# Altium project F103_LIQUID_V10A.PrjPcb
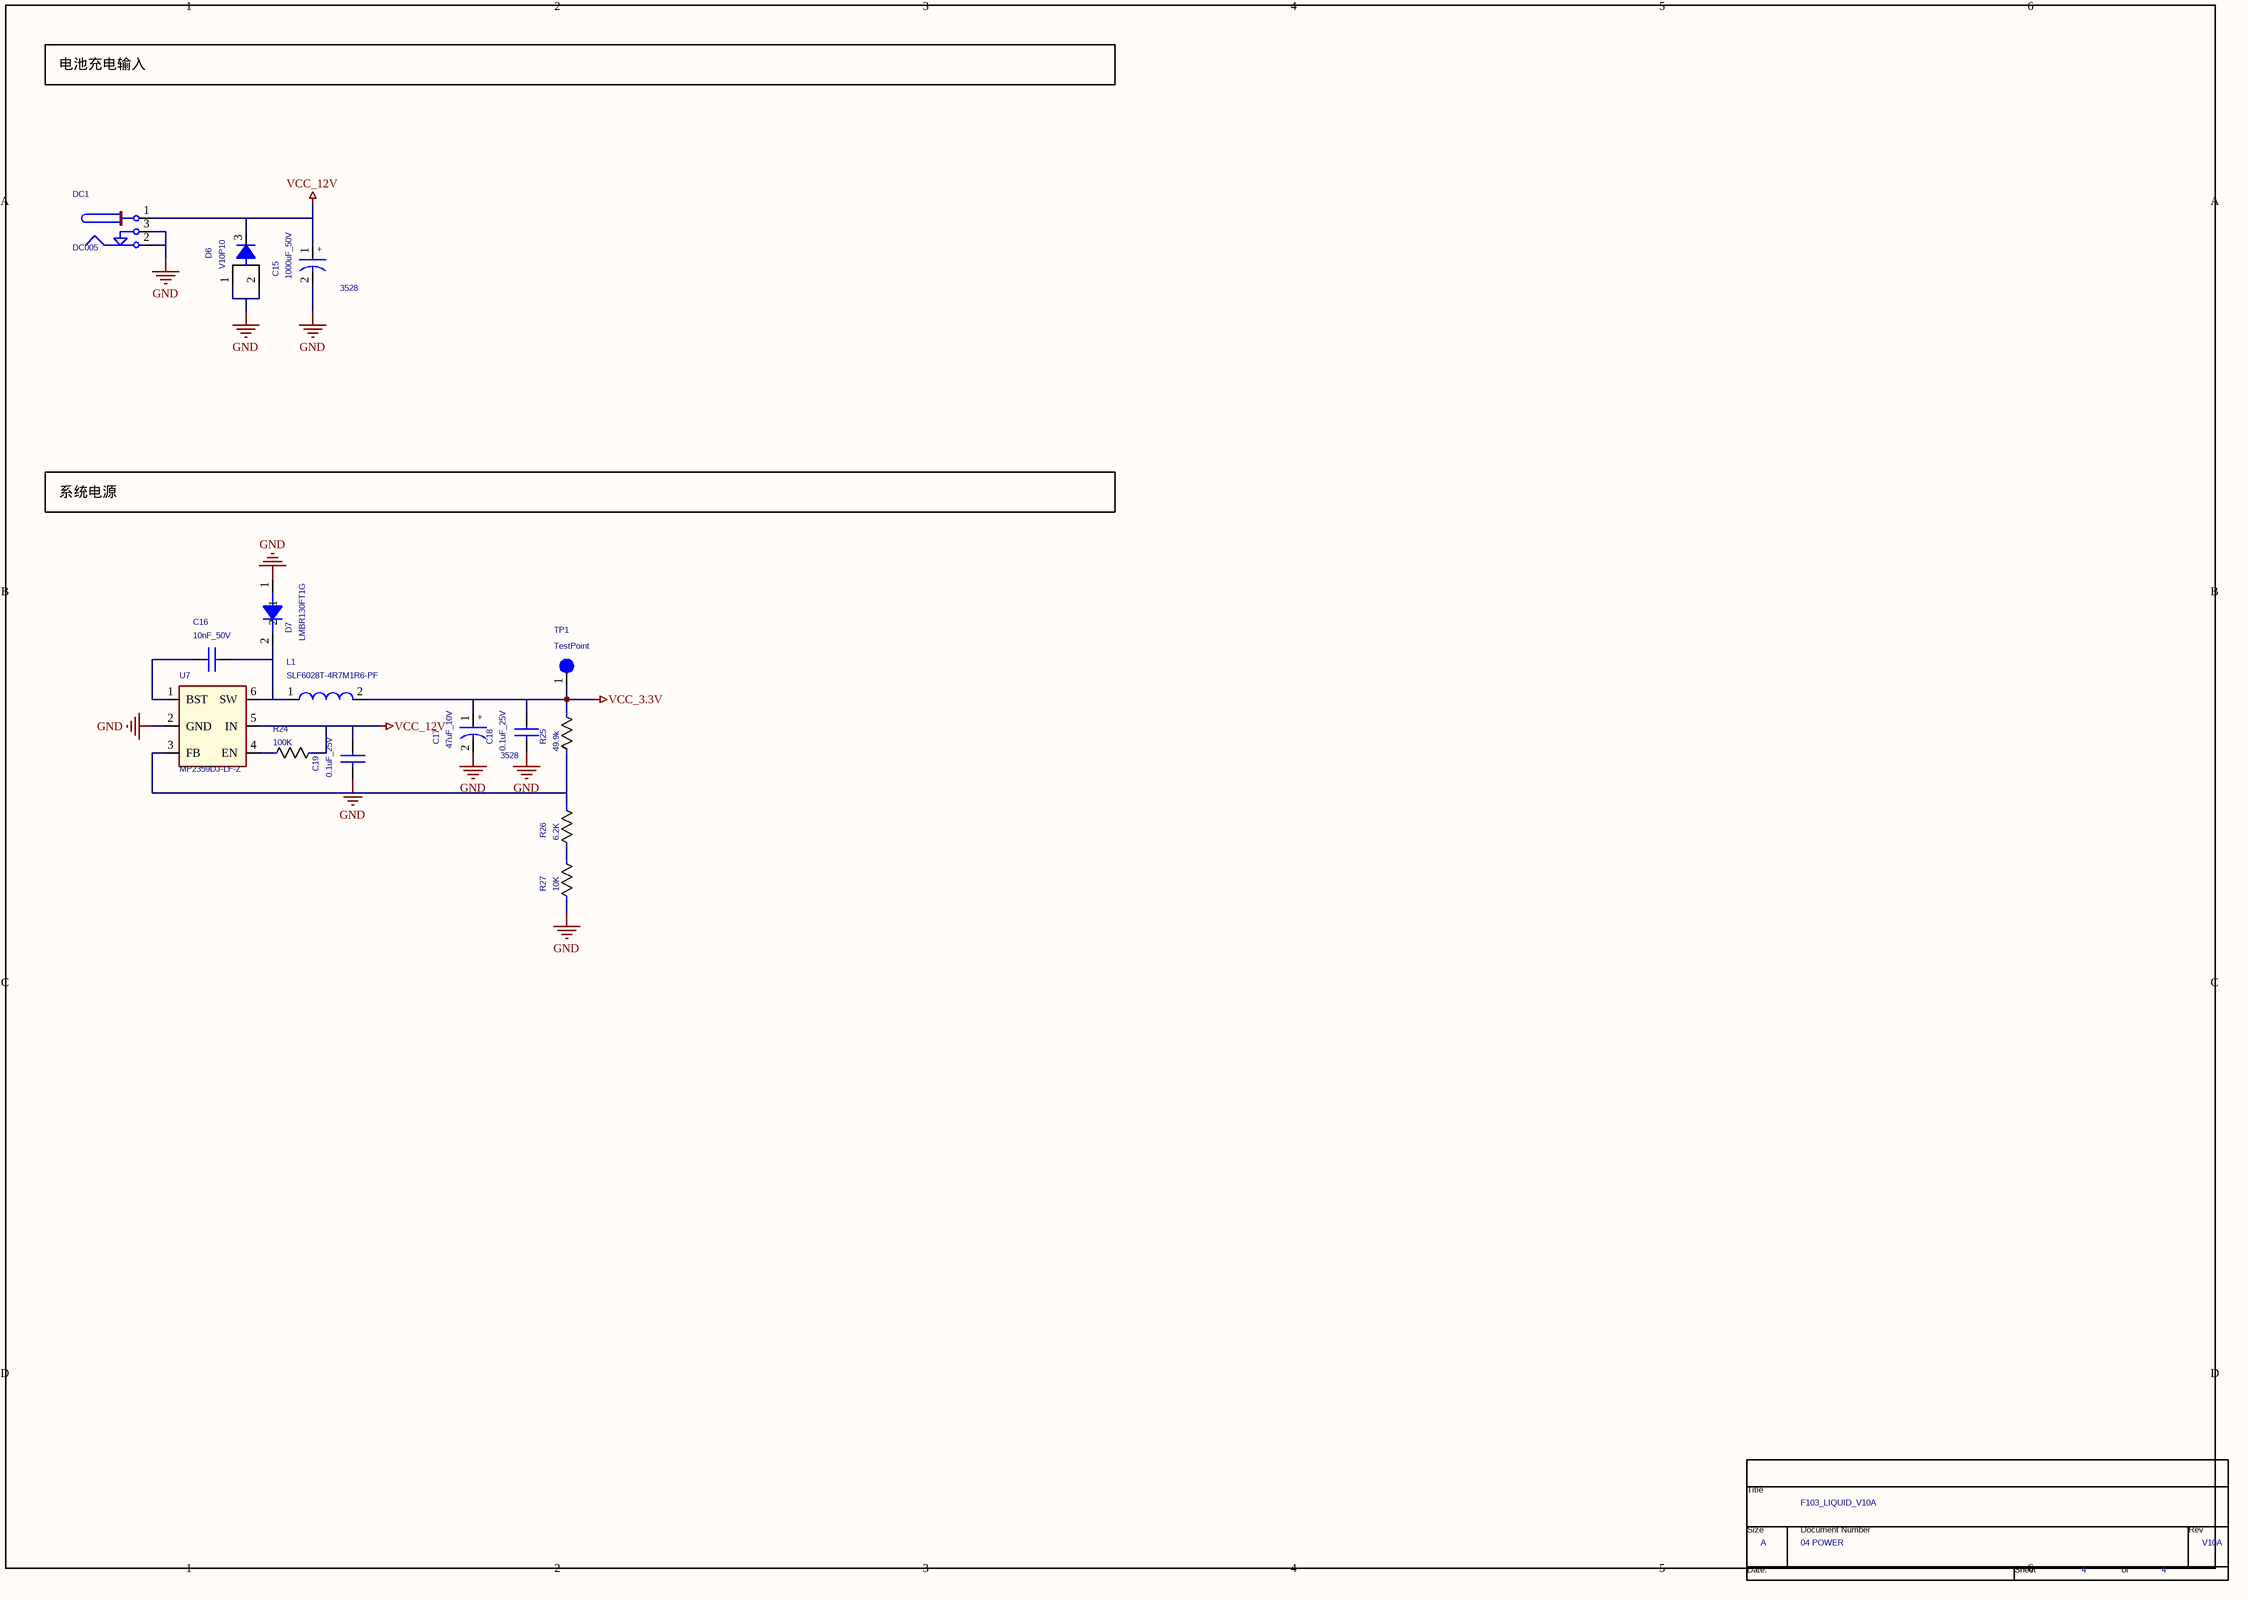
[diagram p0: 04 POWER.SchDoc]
4 sheets, 82 parts. Net scope: global (net labels, ports and power ports of the same name join across sheets).
Board file: F103_LIQUID_V10A.PcbDoc
Sheets:
  04 POWER.SchDoc
  03 RELAY.SchDoc
  02 MCU&TFT.SchDoc
  01 COVER.SchDoc

## Sheet 04 POWER.SchDoc
size 420 x 297 mm

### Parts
(Parts that share a designator on the sheet are numbered #1, #2 ... from top to bottom, then left to right.)
*#1  Doc: 04 POWER  RevCode: V10A  Title: F103_LIQUID_V10A  Page Size: A  Page Number: 4  (hidden comment: TitleBlock0)  (graphical)
C15  1000uF_50V  Shape: 3528  [CT_3528_IPC]
C16  10nF_50V  [C0603]
C17  47uF_10V  Shape: 3528  [CT_3528_IPC]
C18  0.1uF_25V  [C0603]
C19  0.1uF_25V  [C0603]
D6  V10P10  [TO-227A]
D7  LMBR130FT1G  [SOD123]
DC1  DC005  [DC005]
L1  SLF6028T-4R7M1R6-PF  [L6028]
R24  100K  [R0603]
R25  49.9k  [R0603]
R26  6.2K  [R0603]
R27  10K  [R0603]
TP1  TestPoint  [TP-0R75]
U7  MP2359DJ-LF-Z  [TSOT23-6]

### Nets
GND: C15.2 C17.2 C18.2 C19.2 D6.1(ANODE_1) D6.2(ANODE_2) D7.1 DC1.2 DC1.3 R27.2 U7.2(GND)
VCC_3.3V: C17.1 C18.1 L1.2 R25.1 TP1.1
VCC_12V: C15.1 C19.1 D6.3(CATHODE) DC1.1 R24.1 U7.5(IN)
NetC16_1: C16.1 U7.1(BST)
NetC16_2: C16.2 D7.2 L1.1 U7.6(SW)
NetR24_2: R24.2 U7.4(EN)
NetR25_2: R25.2 R26.1 U7.3(FB)
NetR26_2: R26.2 R27.1

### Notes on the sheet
- 电池充电输入
- 系统电源

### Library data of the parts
C15 = CAPT_100UF_3528_6r3V_10%_LXXXX: Cap,50V,10x13,ESK337M1HG13RR; GRN: LHR; EP#: P10100000000041; MFGI 2#: KEM: T494B107K006ATH; MFGI 1#: AVX: TPSB107K006R; Board Option: Base; Corporation: SAMXON
C16 = CAP NP_2: CAP,CERM,50V,+/-10%,X7R,0603; Corporation: FH
C17 = TMP_154254: CAP,TAN,TAJB476K010RNJ; EPI#: P10100000000041; Board Option: Base; MFG 2#: KEM: T494B107K006ATH; MFG 1#: AVX: TPSB107K006R; GRN: LHR; Corporation: AVX
C18 C19 = CAP NP: CAP,CERM,+/-10%,X7R,0603; Corporation: FH
D6 = DIODE13_6: Barrier Schottky Rectifier; Corporation: VISHAY; Type: DIODE
D7 = DIODE13_0: SURFACE MOUNT SCHOTTKY BARRIER RECTIFIER; Type: DIODE; Corporation: LRC
DC1 = DC005: Corporation: LC
L1 = INDUCTOR_0
R24-R27 = R_Generic: RES,1%,0.1W,0603; P/N #3: CR10-103J-T; P/N #1: RK73H1JT1002F; Mfg #1: KOA SPEER; Corporation: FH
TP1 = TestPoint_0: Note: NI
U7 = MP2359DJ-LF-Z: 1.2A, 24V, 1.4MHz Step-Down Converter in a TSOT23-6; Corporation: MPS

## Sheet 03 RELAY.SchDoc
size 420 x 297 mm
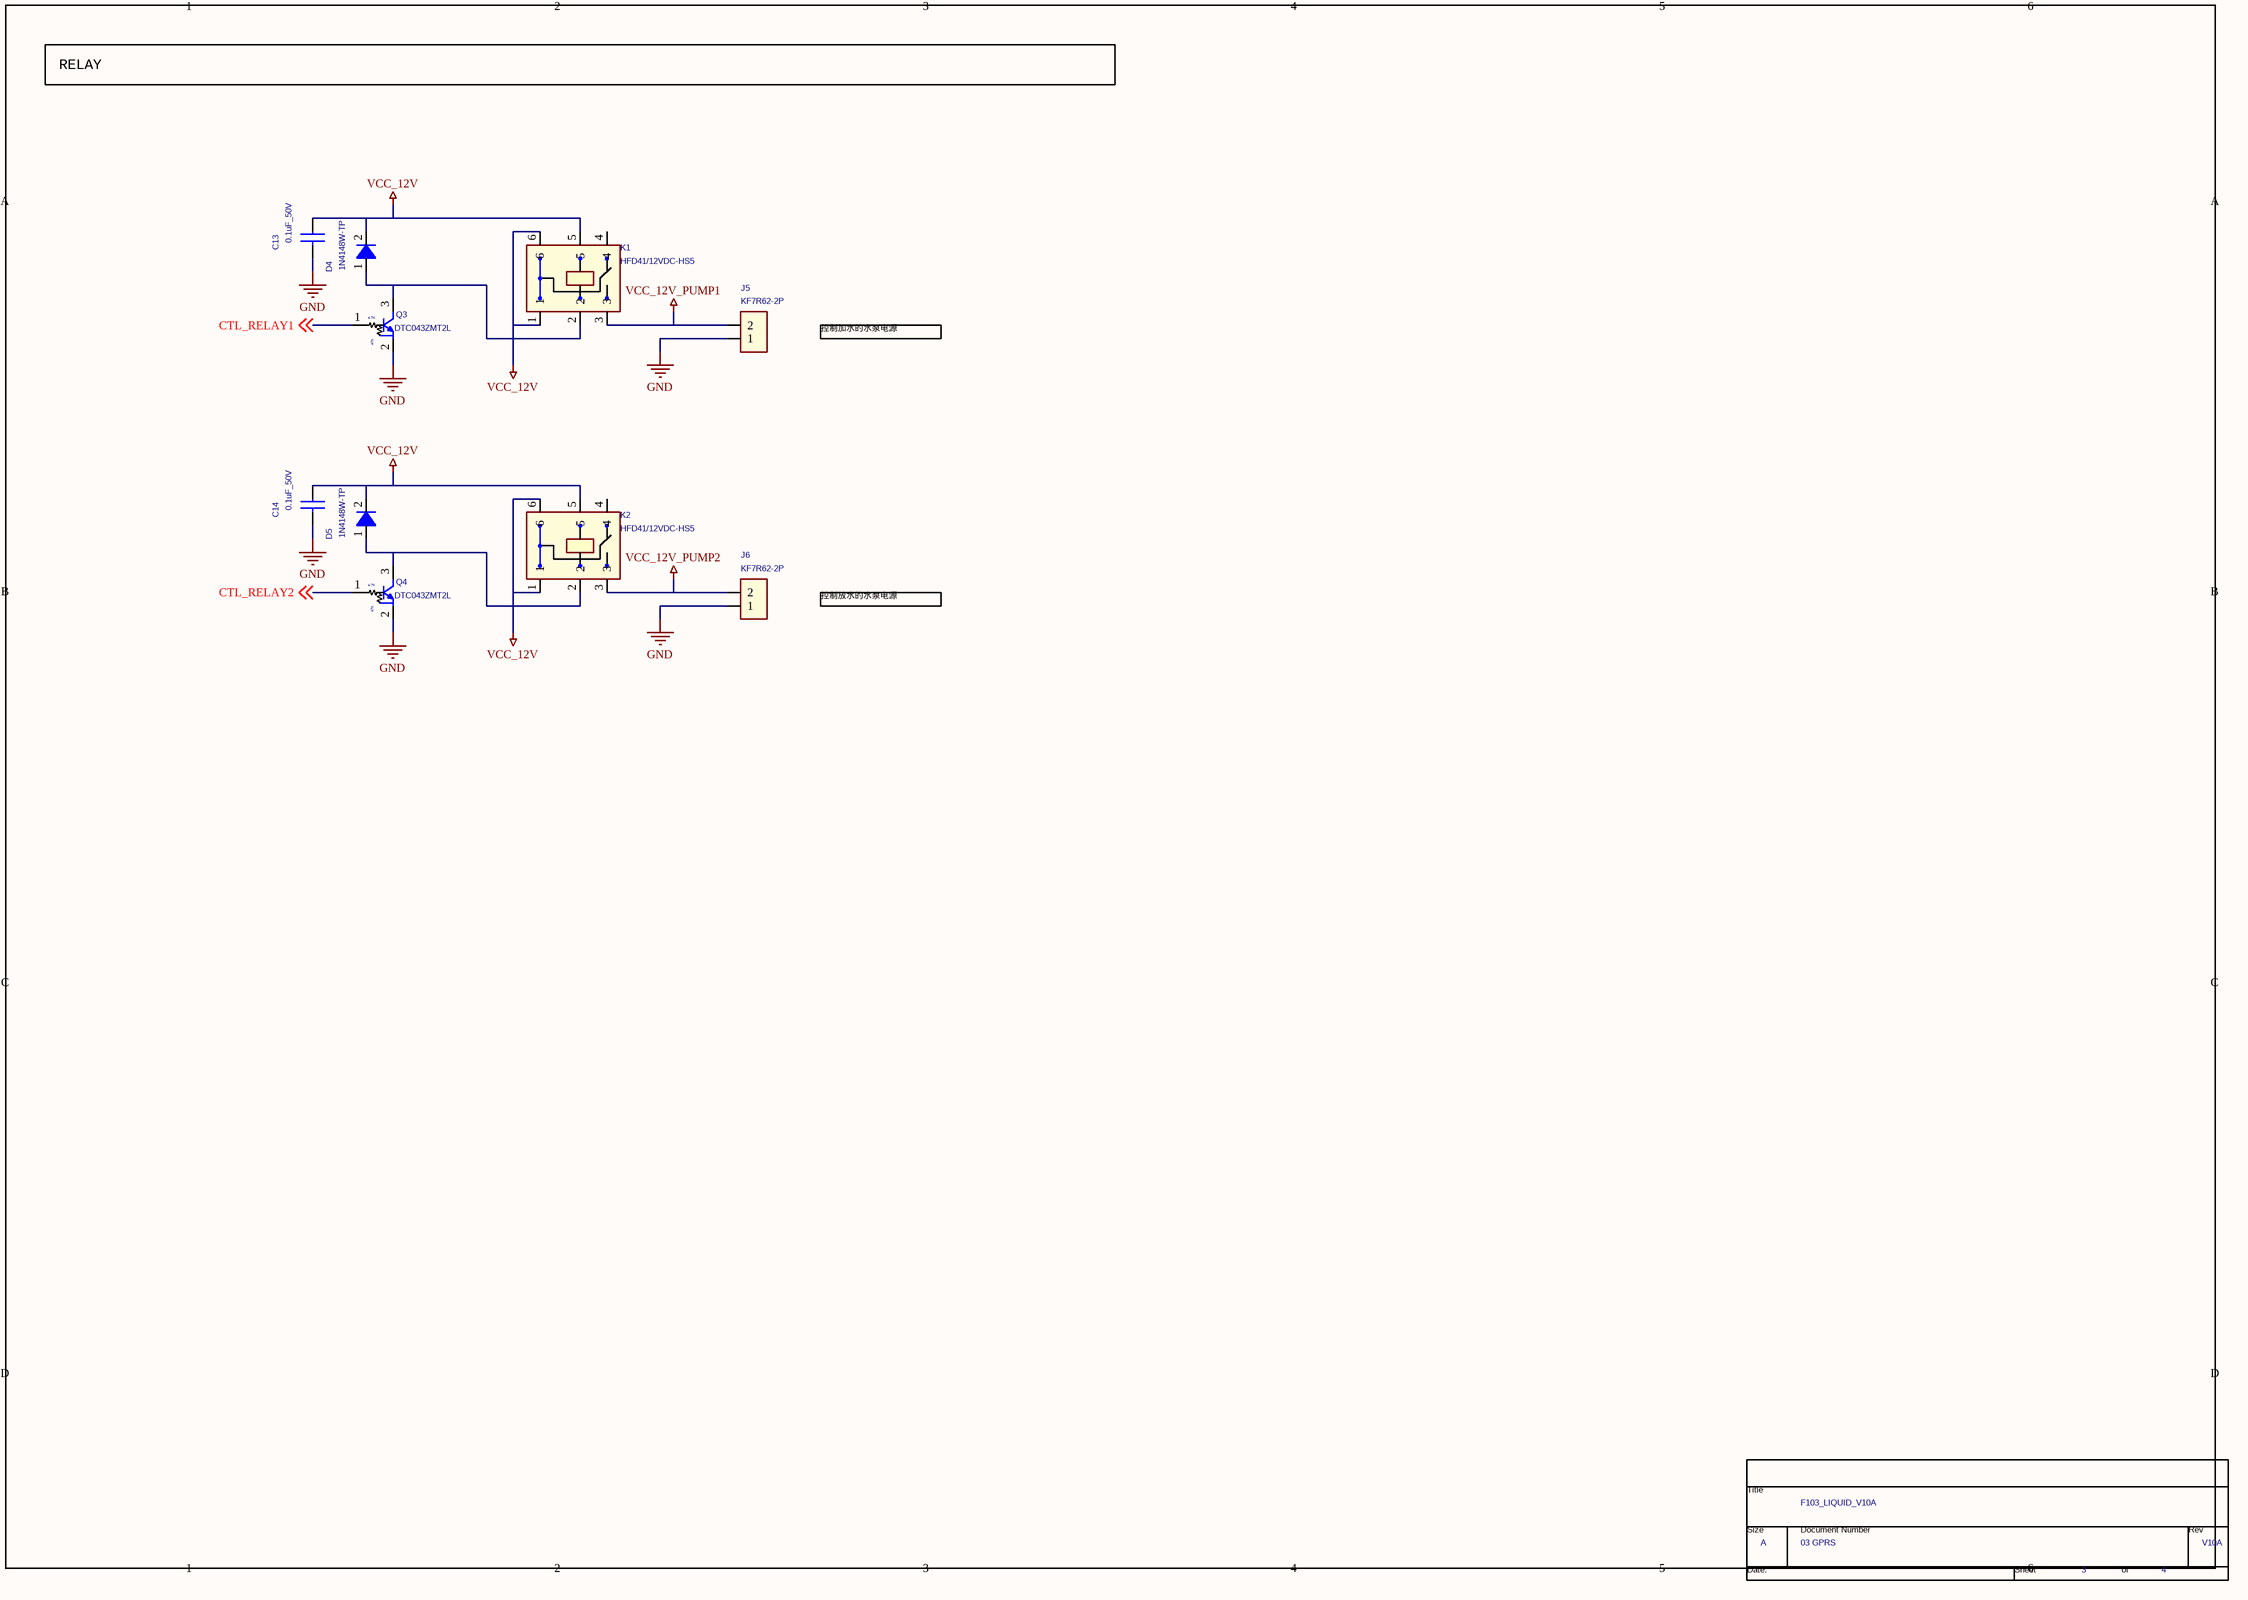
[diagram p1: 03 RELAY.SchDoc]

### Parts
(Parts that share a designator on the sheet are numbered #1, #2 ... from top to bottom, then left to right.)
*#2  Doc: 03 GPRS  RevCode: V10A  Title: F103_LIQUID_V10A  Page Size: A  Page Number: 3  Page Count: 4  (hidden comment: TitleBlock0)  (graphical)
C13  0.1uF_50V  [C0603]
C14  0.1uF_50V  [C0603]
D4  1N4148W-TP  [SOD123]
D5  1N4148W-TP  [SOD123]
J5  KF7R62-2P  [KF7R62-2P]
J6  KF7R62-2P  [KF7R62-2P]
K1  HFD41/12VDC-HS5  [HF32FA-G/005-HSL1]
K2  HFD41/12VDC-HS5  [HF32FA-G/005-HSL1]
Q3  DTC043ZMT2L  [SOT-723]
Q4  DTC043ZMT2L  [SOT-723]

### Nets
GND: C13.2 C14.2 J5.1 J6.1 Q3.2 Q4.2
VCC_12V: C13.1 C14.1 D4.2(CATHODE) D5.2(CATHODE) K1.1 K1.5 K1.6 K2.1 K2.5 K2.6
VCC_12V_PUMP1: J5.2 K1.3
VCC_12V_PUMP2: J6.2 K2.3
CTL_RELAY1: Q3.1 ; off-sheet CTL_RELAY1
CTL_RELAY2: Q4.1 ; off-sheet CTL_RELAY2
NetD4_1: D4.1(ANODE) K1.2 Q3.3
NetD5_1: D5.1(ANODE) K2.2 Q4.3

Not connected (* = marked no-connect by the designer): K1 4; K2 4

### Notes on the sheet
- RELAY
- 控制加水的水泵电源
- 控制放水的水泵电源

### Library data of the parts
C13 C14 = CAP NP_Dup1: CAP,CERM,+/-10%,X7R,0603; Corporation: FH
D4 D5 = DIODE13_7: High Speed Switching Diode 400mW; Corporation: MCC
J5 J6 = HDR_1: Corporation: CIXI MEIGAN
K1 K2 = HF32FA-G/005-HSL1_0: SPST; Corporation: HF
Q3 Q4 = DTC043ZMT2L: Type: NPN; Corporation: ROHM

## Sheet 02 MCU&TFT.SchDoc
size 420 x 297 mm
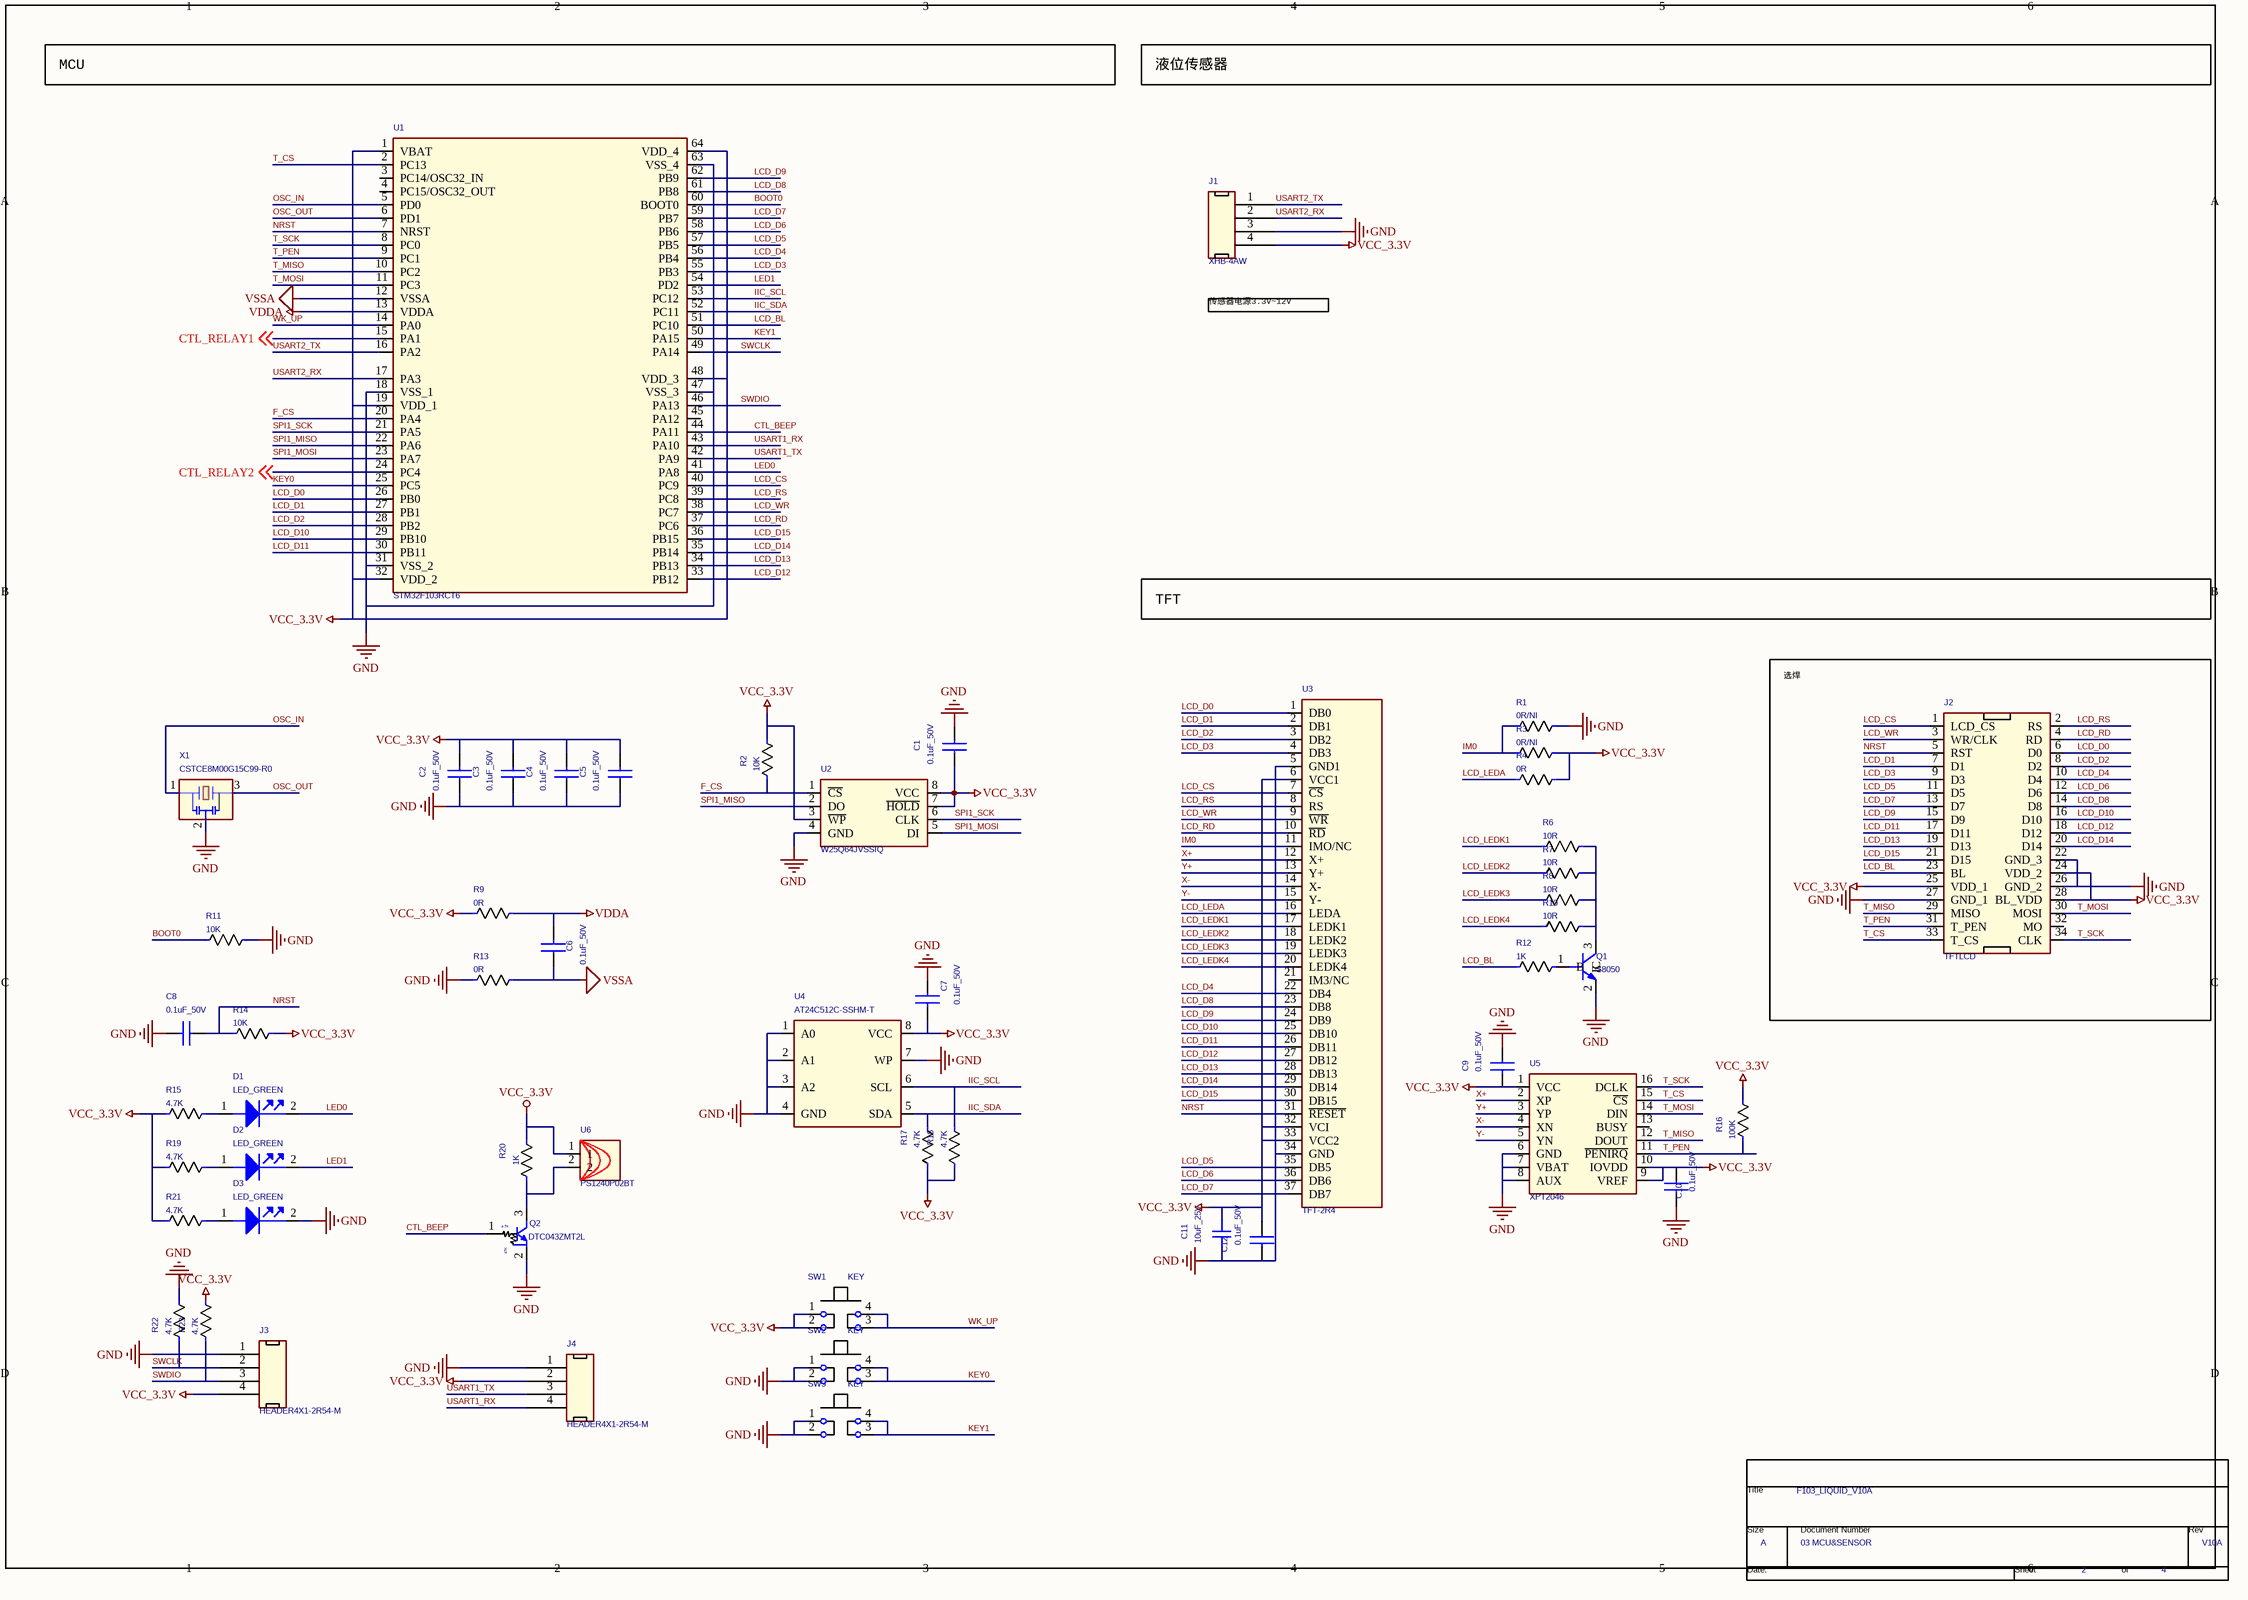
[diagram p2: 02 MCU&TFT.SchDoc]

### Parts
(Parts that share a designator on the sheet are numbered #1, #2 ... from top to bottom, then left to right.)
*#3  Doc: 03 MCU&SENSOR  RevCode: V10A  Title: F103_LIQUID_V10A  Page Size: A  Page Number: 2  Page Count: 4  (hidden comment: TitleBlock0)  (graphical)
C1  0.1uF_50V  [C0603]
C2  0.1uF_50V  [C0603]
C3  0.1uF_50V  [C0603]
C4  0.1uF_50V  [C0603]
C5  0.1uF_50V  [C0603]
C6  0.1uF_50V  [C0603]
C7  0.1uF_50V  [C0603]
C8  0.1uF_50V  [C0603]
C9  0.1uF_50V  [C0603]
C10  0.1uF_50V  [C0603]
C11  10uF_25V  [C0805]
C12  0.1uF_50V  [C0603]
D1  LED_GREEN  [LED0805]
D2  LED_GREEN  [LED0805]
D3  LED_GREEN  [LED0805]
J1  XHB-4AW  [XHB-4AW]
J2  TFTLCD  [TFTLCD_3R5]
J3  HEADER4X1-2R54-M  [HEADER4X1-2R54-M]
J4  HEADER4X1-2R54-M  [HEADER4X1-2R54-M]
Q1  S8050  [SOT23-3]
Q2  DTC043ZMT2L  [SOT-723]
R1  0R/NI  [R0603]
R2  10K  [R0603]
R3  0R/NI  [R0603]
R4  0R  [R0603]
R6  10R  [R0603]
R7  10R  [R0603]
R8  10R  [R0603]
R9  0R  [R0603]
R10  10R  [R0603]
R11  10K  [R0603]
R12  1K  [R0603]
R13  0R  [R0603]
R14  10K  [R0603]
R15  4.7K  [R0603]
R16  100K  [R0603]
R17  4.7K  [R0603]
R18  4.7K  [R0603]
R19  4.7K  [R0603]
R20  1K  [R0603]
R21  4.7K  [R0603]
R22  4.7K  [R0603]
R23  4.7K  [R0603]
SW1  KEY  [SPST]
SW2  KEY  [SPST]
SW3  KEY  [SPST]
U1  STM32F103RCT6  [QFP-64]
U2  W25Q64JVSSIQ  [SO-8-W]
U3  TFT-2R4  [TFT-2R4]
U4  AT24C512C-SSHM-T  [SOIC8]
U5  XPT2046  [TSSOP-16]
U6  PS1240P02BT  [PS1240P02BT]
X1  CSTCE8M00G15C99-R0  [XTAL_5032]

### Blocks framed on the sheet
选焊: J2

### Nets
GND: C1.2 C2.1 C3.1 C4.1 C5.1 C7.1 C8.2 C9.1 C10.2 C11.2 C12.2 D3.2(CATHODE) J1.3 J2.22(GND_3) J2.26(GND_2) J2.27(GND_1) J3.1 J4.1 Q1.2(E) Q2.2 R1.2 R11.2 R13.2 R22.1 SW2.1 SW2.2 SW3.1 SW3.2 U1.18(VSS_1) U1.31(VSS_2) U1.47(VSS_3) U1.63(VSS_4) U2.4(GND) U3.5(GND1) U3.34(GND) U4.1(A0) U4.2(A1) U4.3(A2) U4.4(GND) U4.7(WP) U5.6(GND) U5.7(VBAT) U5.8(AUX) X1.2
VCC_3.3V: C1.1 C2.2 C3.2 C4.2 C5.2 C7.2 C9.2 C10.1 C11.1 C12.1 J1.4 J2.24(VDD_2) J2.25(VDD_1) J2.28(BL_VDD) J3.4 J4.2 R2.1 R3.2 R4.2 R9.2 R14.1 R15.1 R16.1 R17.2 R18.2 R19.1 R20.1 R21.1 R23.1 SW1.1 SW1.2 U1.1(VBAT) U1.19(VDD_1) U1.32(VDD_2) U1.48(VDD_3) U1.64(VDD_4) U2.3(~{WP}) U2.7(~{HOLD}) U2.8(VCC) U3.6(VCC1) U3.32(VCI) U3.33(VCC2) U4.8(VCC) U5.1(VCC) U5.9(VREF) U5.10(IOVDD) U6.1
VDDA: C6.2 R9.1 U1.13(VDDA)
VSSA: C6.1 R13.1 U1.12(VSSA)
BOOT0: R11.1 U1.60(BOOT0)
CTL_BEEP: Q2.1 U1.44(PA11)
CTL_RELAY1: U1.15(PA1) ; off-sheet CTL_RELAY1
CTL_RELAY2: U1.24(PC4) ; off-sheet CTL_RELAY2
F_CS: R2.2 U1.20(PA4) U2.1(~{CS})
IIC_SCL: R18.1 U1.53(PC12) U4.6(SCL)
IIC_SDA: R17.1 U1.52(PC11) U4.5(SDA)
IM0: R1.1 R3.1 U3.11(IMO/NC)
KEY0: SW2.3 SW2.4 U1.25(PC5)
KEY1: SW3.3 SW3.4 U1.50(PA15)
LCD_BL: J2.23(BL) R12.1 U1.51(PC10)
LCD_CS: J2.1(LCD_CS) U1.40(PC9) U3.7(~{CS})
LCD_D0: J2.6(D0) U1.26(PB0) U3.1(DB0)
LCD_D1: J2.7(D1) U1.27(PB1) U3.2(DB1)
LCD_D2: J2.8(D2) U1.28(PB2) U3.3(DB2)
LCD_D3: J2.9(D3) U1.55(PB3) U3.4(DB3)
LCD_D4: J2.10(D4) U1.56(PB4) U3.22(DB4)
LCD_D5: J2.11(D5) U1.57(PB5) U3.35(DB5)
LCD_D6: J2.12(D6) U1.58(PB6) U3.36(DB6)
LCD_D7: J2.13(D7) U1.59(PB7) U3.37(DB7)
LCD_D8: J2.14(D8) U1.61(PB8) U3.23(DB8)
LCD_D9: J2.15(D9) U1.62(PB9) U3.24(DB9)
LCD_D10: J2.16(D10) U1.29(PB10) U3.25(DB10)
LCD_D11: J2.17(D11) U1.30(PB11) U3.26(DB11)
LCD_D12: J2.18(D12) U1.33(PB12) U3.27(DB12)
LCD_D13: J2.19(D13) U1.34(PB13) U3.28(DB13)
LCD_D14: J2.20(D14) U1.35(PB14) U3.29(DB14)
LCD_D15: J2.21(D15) U1.36(PB15) U3.30(DB15)
LCD_LEDA: R4.1 U3.16(LEDA)
LCD_LEDK1: R6.1 U3.17(LEDK1)
LCD_LEDK2: R7.1 U3.18(LEDK2)
LCD_LEDK3: R8.1 U3.19(LEDK3)
LCD_LEDK4: R10.1 U3.20(LEDK4)
LCD_RD: J2.4(RD) U1.37(PC6) U3.10(~{RD})
LCD_RS: J2.2(RS) U1.39(PC8) U3.8(RS)
LCD_WR: J2.3(WR/CLK) U1.38(PC7) U3.9(~{WR})
LED0: D1.2(CATHODE) U1.41(PA8)
LED1: D2.2(CATHODE) U1.54(PD2)
NRST: C8.1 J2.5(RST) R14.2 U1.7(NRST) U3.31(~{RESET})
OSC_IN: U1.5(PD0) X1.1
OSC_OUT: U1.6(PD1) X1.3
SPI1_MISO: U1.22(PA6) U2.2(DO)
SPI1_MOSI: U1.23(PA7) U2.5(DI)
SPI1_SCK: U1.21(PA5) U2.6(CLK)
SWCLK: J3.2 R22.2 U1.49(PA14)
SWDIO: J3.3 R23.2 U1.46(PA13)
T_CS: J2.33(T_CS) U1.2(PC13) U5.15(~{CS})
T_MISO: J2.29(MISO) U1.10(PC2) U5.12(DOUT)
T_MOSI: J2.30(MOSI) U1.11(PC3) U5.14(DIN)
T_PEN: J2.31(T_PEN) R16.2 U1.9(PC1) U5.11(~{PENIRQ})
T_SCK: J2.34(CLK) U1.8(PC0) U5.16(DCLK)
USART1_RX: J4.4 U1.43(PA10)
USART1_TX: J4.3 U1.42(PA9)
USART2_RX: J1.2 U1.17(PA3)
USART2_TX: J1.1 U1.16(PA2)
WK_UP: SW1.3 SW1.4 U1.14(PA0)
X+: U3.12(X+) U5.2(XP)
X-: U3.14(X-) U5.4(XN)
Y+: U3.13(Y+) U5.3(YP)
Y-: U3.15(Y-) U5.5(YN)
NetD1_1: D1.1(ANODE) R15.2
NetD2_1: D2.1(ANODE) R19.2
NetD3_1: D3.1(ANODE) R21.2
NetQ1_1: Q1.1(B) R12.2
NetQ1_3: Q1.3(C) R6.2 R7.2 R8.2 R10.2
NetQ2_3: Q2.3 R20.2 U6.2

Not connected (* = marked no-connect by the designer): J2 32(MO); U1 3(PC14/OSC32_IN) 4(PC15/OSC32_OUT) 45(PA12); U3 21(IM3/NC); U5 13(BUSY)

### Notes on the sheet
- MCU
- 液位传感器
- 传感器电源3.3V
  2V
- TFT

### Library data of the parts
C1-C6 = CAP NP_2: CAP,CERM,+/-10%,X7R,0603; Corporation: FH
C7 = CAP NP_3: CAP,CERM,+/-10%,X7R,0603; Corporation: FH
C8 = CAP NP: as C18 on sheet 04 POWER
C9 C10 C12 = CAP NP_Dup1: as C13 on sheet 03 RELAY
C11 = C_Generic: CAP,CERM,+/-10%,X5R,0805; Dielectric: X7R; Mfg #1: KEMET; Voltage: 16V; P/N #1: C0603C104K4RAC; Toler.: 10%; Corporation: FH
D1-D3 = LED_4: vend_part_desc: DIGI-KEY;PANASONIC; Vend_part_no: P525CT-ND;LNJ308G8TRA; BRCMPN: 106336-00; Type: LED; Second_Description: SING DIF; Vendor_Name: DIGI-KEY;VENDOR TO BE DETERMINED; Specs: 0603
J1 = CONN RCPT 4_Dup1
J2 = CONN RCPT 17x2_1
J3 J4 = CONN RCPT 4_Dup1: Corporation: NEXTRON
Q1 = L14G1/TO_1: SOT-23 Plastic-Encapsulate Transistors; Corporation: CJ; Type: NPN
Q2 = DTC043ZMT2L: Type: NPN; Corporation: ROHM
R1-R4 R6-R23 = R_Generic: as R24 on sheet 04 POWER
SW1-SW3 = SWITCH-SPST-4P: SW-B3F4055; Corporation: OMRON
U1 = STM32F103RxT6: ST Cortex-m3 MCU
U2 = W25Qxx: 3V 64M-BIT SPI FLASH; Corporation: WINBOND
U3 = TFT-2R4: ILI9341 2.4 TFT; Corporation: ILI
U4 = AT24C512: Corporation: MICROCHIP
U5 = XPT2046: Touch Screen Controller; Corporation: XPT
U6 = PS1240P02BT: Corporation: TDK
X1 = XTAL_5032_0: Corporation: muRata

## Sheet 01 COVER.SchDoc
size 420 x 297 mm
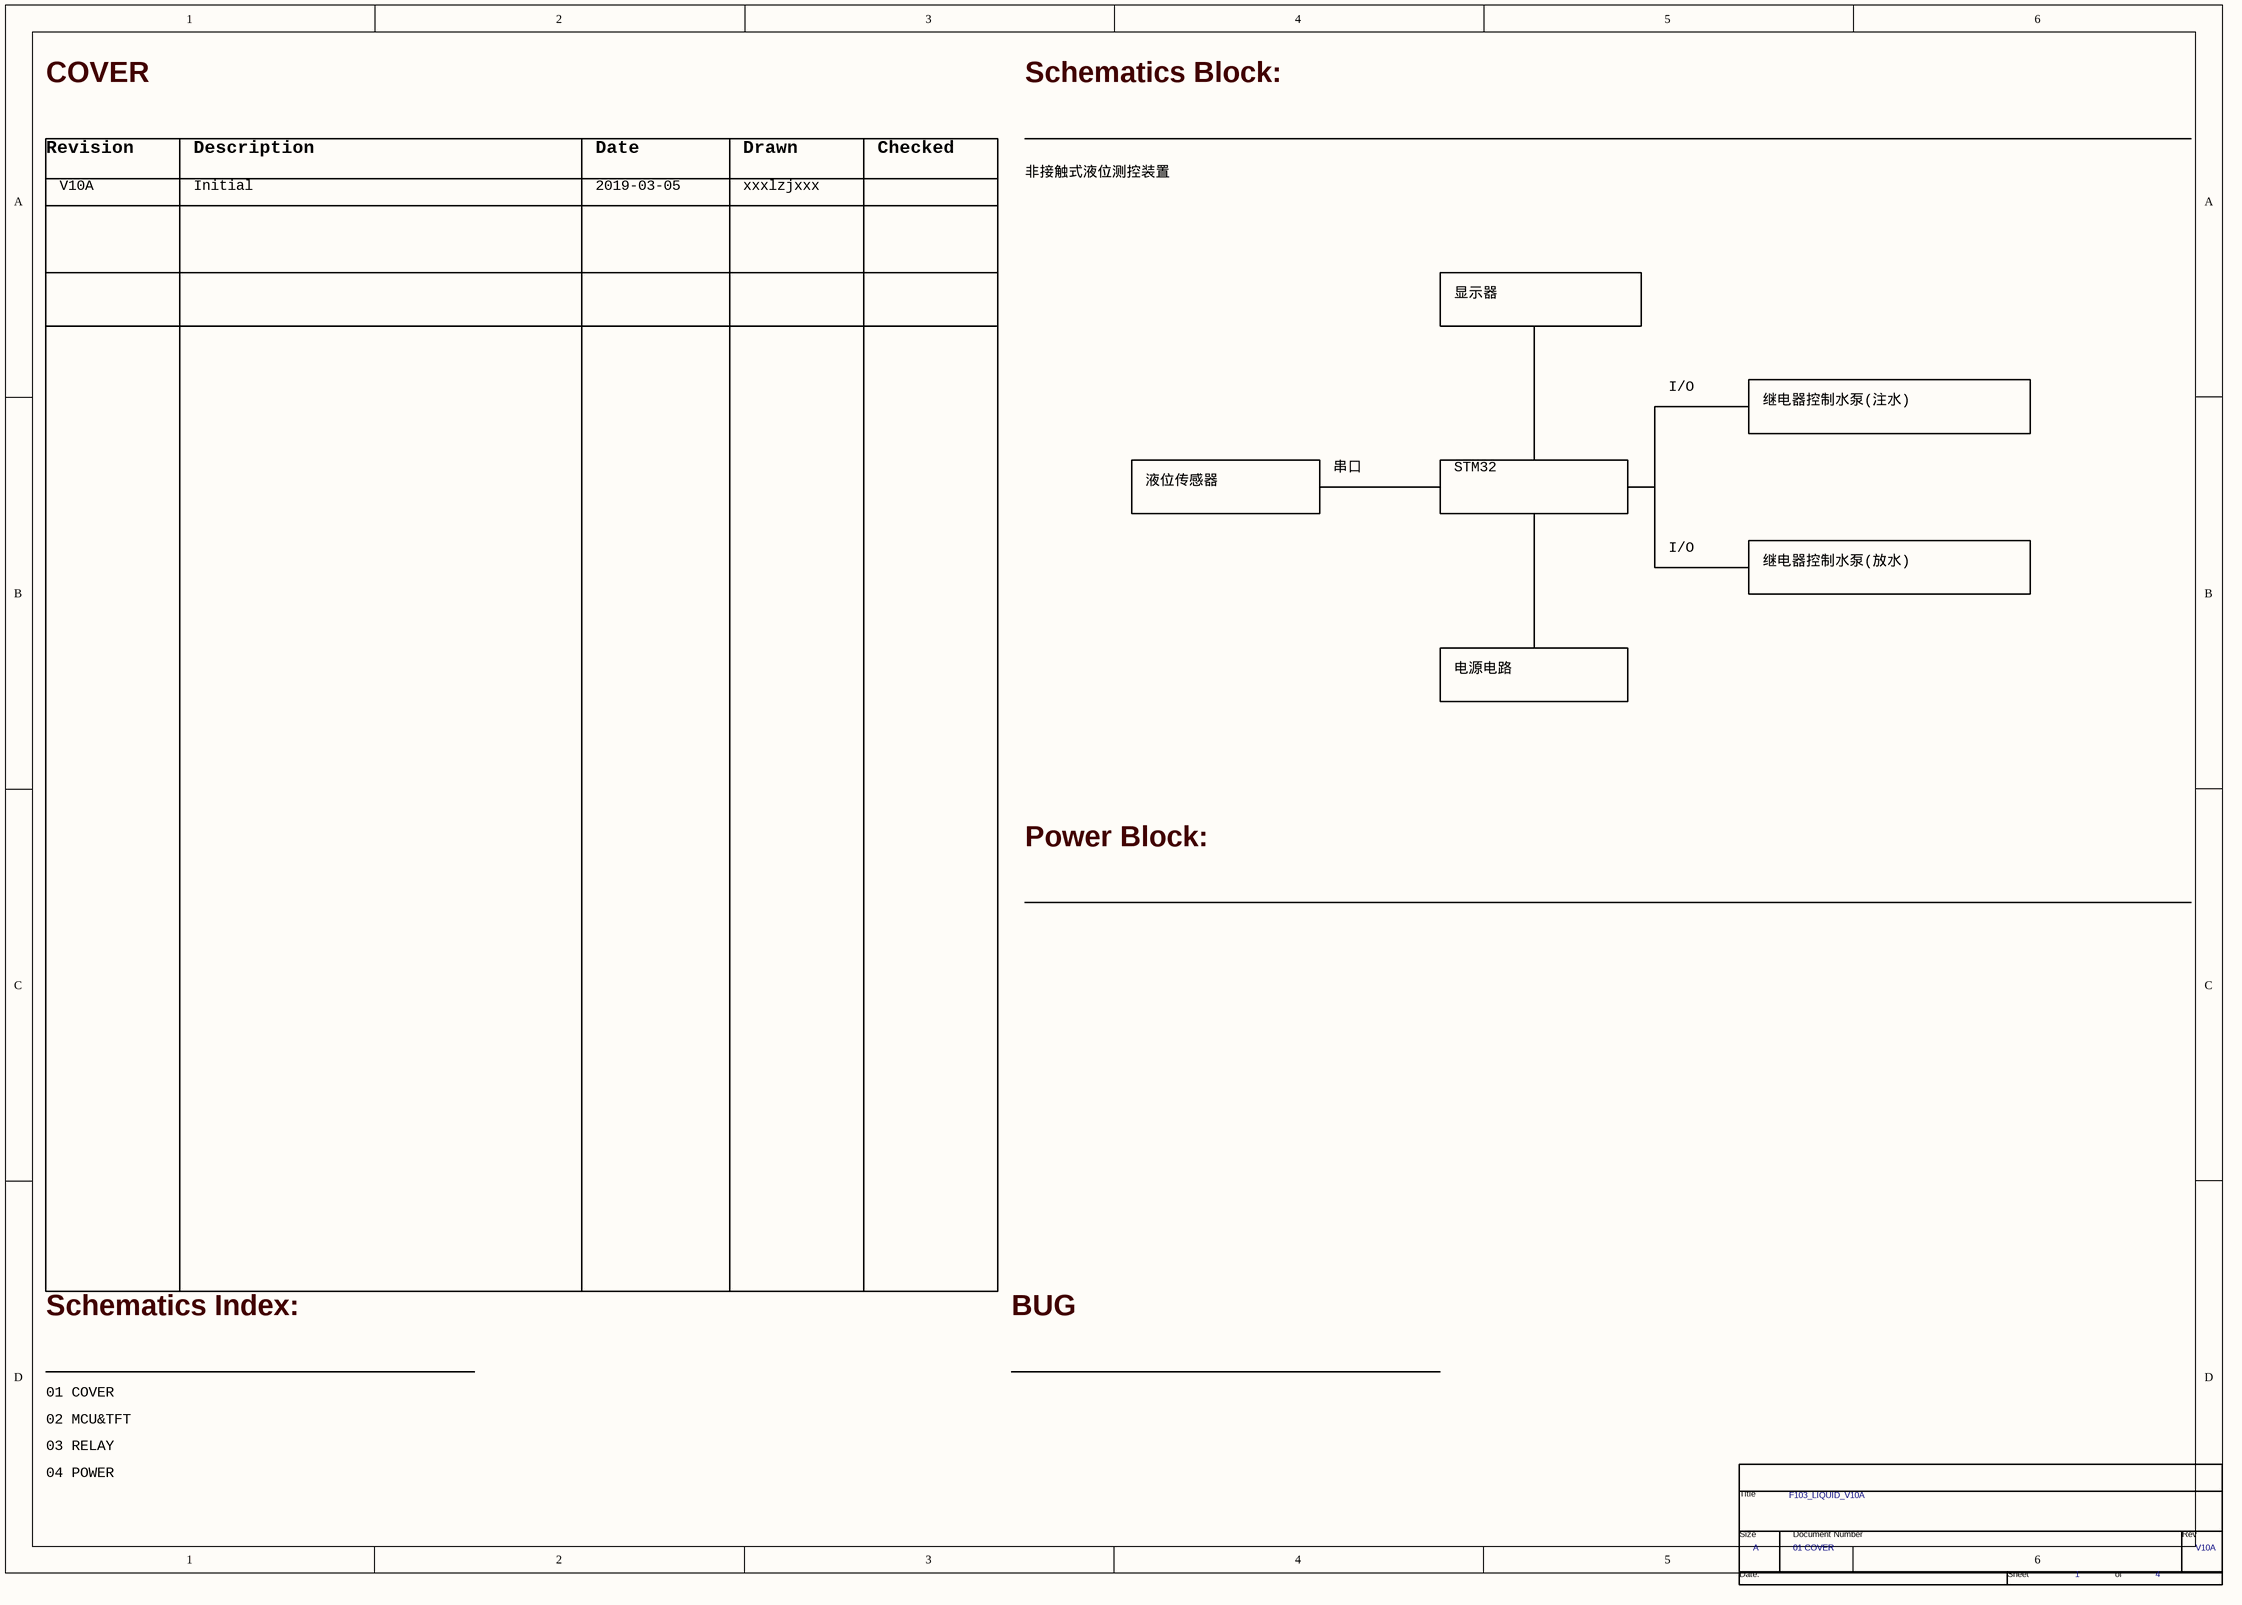
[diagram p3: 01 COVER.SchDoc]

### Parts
(Parts that share a designator on the sheet are numbered #1, #2 ... from top to bottom, then left to right.)
*#4  Doc: 01 COVER  RevCode: V10A  Title: F103_LIQUID_V10A  Page Size: A  Page Number: 1  Page Count: 4  (hidden comment: TitleBlock0)  (graphical)

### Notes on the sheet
- COVER
- Schematics Block:
- Revision
- V10A
- Description
- Initial
- Date
- 2019-03-05
- Drawn
- xxxlzjxxx
- Checked
- 非接触式液位测控装置
- 显示器
- I/O
- 继电器控制水泵(注水)
- 液位传感器
- 串口
- STM32
- 继电器控制水泵(放水)
- 电源电路
- Power Block:
- Schematics Index:
- BUG
- 01 COVER
- 03 RELAY
- 02 MCU&TFT
- 04 POWER

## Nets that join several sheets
GND: 04 POWER (11 pins), 03 RELAY (6 pins), 02 MCU&TFT (44 pins)
VCC_3.3V: 04 POWER (5 pins), 02 MCU&TFT (47 pins)
VCC_12V: 04 POWER (6 pins), 03 RELAY (10 pins)
CTL_RELAY1: 03 RELAY (Q3.1), 02 MCU&TFT (U1.15)
CTL_RELAY2: 03 RELAY (Q4.1), 02 MCU&TFT (U1.24)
